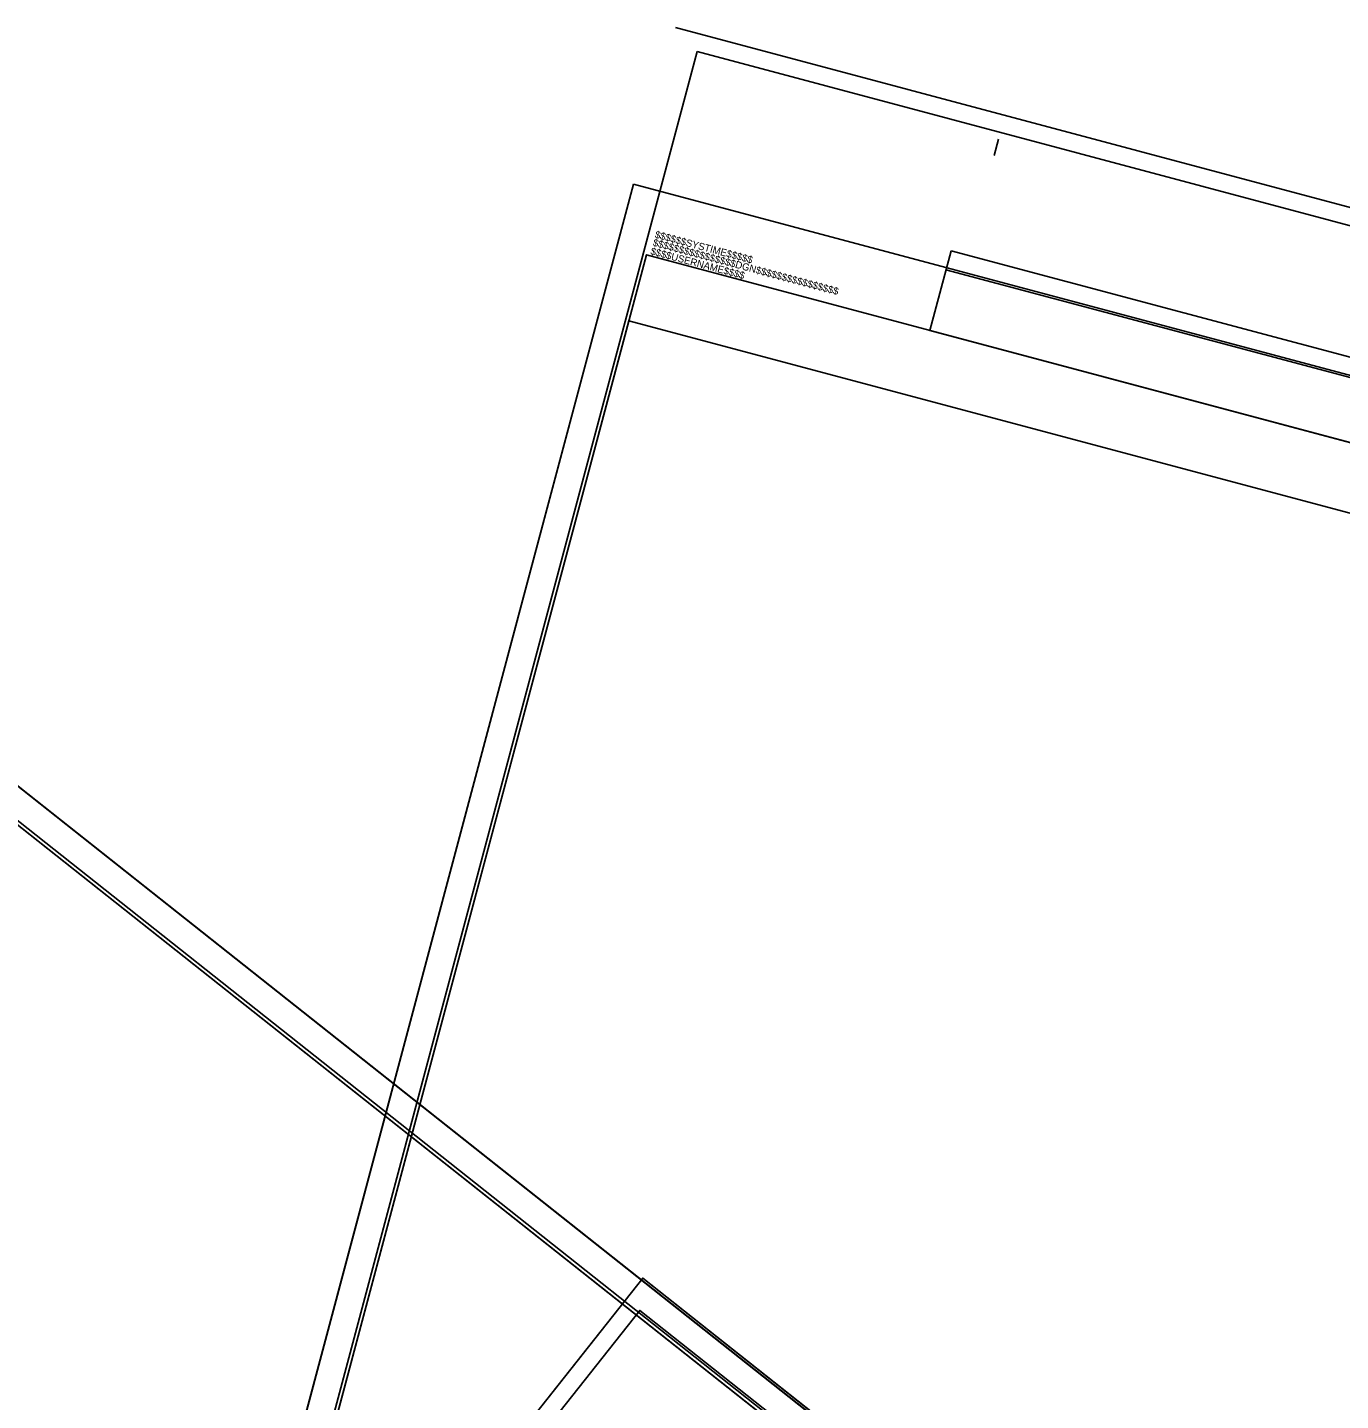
# Model space of a CAD drawing. Extents: x 1778994 to 1784559, y 810461 to 816654.
# Drawn here: x 1782142 to 1783105, y 815048 to 816054 of the extents above; entities that cross this region are included whole.
import ezdxf

# ---------------------------------------------------------------- set-up
doc = ezdxf.new("R2010")
doc.units = 0
for name, color, linetype in [('Sheet Block Revision CELL', 7, 'Continuous'), ('Sheet Clip Boundary CELL', 7, 'Continuous'), ('Sheet Cutting Line CELL', 7, 'Continuous'), ('Sheet Layout Plan Border', 7, 'Continuous'), ('Sheet Plan CELL', 7, 'Continuous'), ('Sheet Plan Layout CELL', 7, 'Continuous'), ('Sheet Plot Border Inside CELL', 7, 'Continuous'), ('Sheet Plot Border Outside CELL', 7, 'Continuous')]:
    doc.layers.add(name, color=color, linetype=linetype)

msp = doc.modelspace()

# ---------------------------------------------------------------- linework, layer by layer
at = {"layer": 'Sheet Block Revision CELL'}
msp.add_line((1782815.8, 815876.7), (1783579.7, 815672.9), dxfattribs=at)
msp.add_lwpolyline([(1782819.5, 815890.7), (1783583.5, 815687), (1783567.9, 815628.5), (1782804, 815832.2)], close=True, dxfattribs=at)
at = {"layer": 'Sheet Clip Boundary CELL'}
for points in [[(1782583.3, 815839.3), (1782222.6, 814486.6), (1783032.8, 814270.5), (1783081.5, 814453.4), (1783285.9, 814398.9), (1783597.9, 815568.8)], [(1781330.1, 814767.8), (1782427.7, 813898.8), (1782948.2, 814556.2), (1782799.8, 814673.7), (1782931.1, 814839.5), (1781981.8, 815591.1)]]:
    msp.add_lwpolyline(points, close=True, dxfattribs=at)
at = {"layer": 'Sheet Cutting Line CELL'}
for p, q in [((1783675.4, 815772.2), (1782617.4, 816054.3)), ((1782586.7, 815939.4), (1782152.9, 814312.8)), ((1783087.4, 814744.4), (1781767.5, 815789.4)), ((1782593.5, 815137.7), (1781913.8, 814279.2)), ((1783913.4, 814092.8), (1782593.5, 815137.7))]:
    msp.add_line(p, q, dxfattribs=at)
at = {"layer": 'Sheet Layout Plan Border'}
for points in [[(1782583.3, 815839.3), (1782222.6, 814486.6), (1783032.8, 814270.5), (1783081.5, 814453.4), (1783285.9, 814398.9), (1783597.9, 815568.8)], [(1781330.1, 814767.8), (1782427.7, 813898.8), (1782948.2, 814556.2), (1782799.8, 814673.7), (1782931.1, 814839.5), (1781981.8, 815591.1)]]:
    msp.add_lwpolyline(points, close=True, dxfattribs=at)
at = {"layer": 'Sheet Plan CELL'}
for p, q in [((1782854.3, 815972.5), (1782851.1, 815960.4)), ((1782596.2, 815887.7), (1782596.2, 815887.7))]:
    msp.add_line(p, q, dxfattribs=at)
for points in [[(1783224.2, 814167.7), (1783610.8, 815617.1), (1782596.2, 815887.7), (1782209.7, 814438.3)], [(1782596.2, 815887.7), (1783610.7, 815617.1), (1783275.8, 814361), (1783130.8, 814399.7), (1783079.2, 814206.4), (1782209.7, 814438.3)], [(1783060.1, 814737.4), (1781884.1, 815668.5), (1781232.3, 814845.2), (1782408.4, 813914.1)], [(1781232.3, 814845.2), (1781884, 815668.5), (1782903.3, 814861.6), (1782810.1, 814743.9), (1782967, 814619.7), (1782408.4, 813914.1)]]:
    msp.add_lwpolyline(points, close=True, dxfattribs=at)
at = {"layer": 'Sheet Plan Layout CELL'}
for points in [[(1783610.7, 815617.1), (1782596.2, 815887.7), (1782209.7, 814438.3), (1783019.9, 814222.2), (1783081.5, 814453.4), (1783285.9, 814398.9)], [(1781884, 815668.5), (1781232.3, 814845.2), (1782408.3, 813914.1), (1782928.8, 814571.6), (1782741.3, 814720.1), (1782872.5, 814885.9)]]:
    msp.add_lwpolyline(points, close=True, dxfattribs=at)
at = {"layer": 'Sheet Plot Border Inside CELL'}
for points in [[(1782633.3, 816036.6), (1782204.1, 814426.9), (1783223.4, 814155), (1783652.7, 815764.7)], [(1781110.4, 814938.5), (1782416.6, 813904.4), (1783071.5, 814731.6), (1781765.3, 815765.7)], [(1781936.4, 814286.8), (1783242.6, 813252.7), (1783897.5, 814079.9), (1782591.3, 815114)]]:
    msp.add_lwpolyline(points, close=True, dxfattribs=at)
at = {"layer": 'Sheet Plot Border Outside CELL'}
for points in [[(1782586.7, 815939.4), (1782152.9, 814312.8), (1783210.9, 814030.6), (1783644.8, 815657.3)], [(1781087.8, 814930.9), (1782407.7, 813885.9), (1783087.4, 814744.4), (1781767.5, 815789.4)], [(1781913.8, 814279.2), (1783233.7, 813234.2), (1783913.4, 814092.8), (1782593.5, 815137.7)]]:
    msp.add_lwpolyline(points, close=True, dxfattribs=at)

# ---------------------------------------------------------------- texts
at = {"layer": 'Sheet Plan CELL'}
for s, p in [('$$$$$$$$$$$$$$$$DGN$$$$$$$$$$$$$$$$', (1782600.5, 815894.4)), ('$$$$$$SYSTIME$$$$$', (1782602, 815900.3)), ('$$$$USERNAME$$$$', (1782598.8, 815888.1))]:
    msp.add_text(s, height=5.25, rotation=345.0673, dxfattribs=at).set_placement(p)

doc.saveas('drawing.dxf')
